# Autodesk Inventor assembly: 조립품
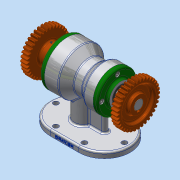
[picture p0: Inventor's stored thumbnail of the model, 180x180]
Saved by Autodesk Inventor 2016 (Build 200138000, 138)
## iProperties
Created: 2020-01
Part Number: 조립품
Document SubType Name: Assembly
Designer: woori
Author: woori
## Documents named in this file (13)
- C:\Users\woori\Desktop\700104v1001\조립품.iam
- C:\Users\woori\Desktop\700104v1001\본체.ipt
- C:\Users\woori\Desktop\700104v1001\뒤커버.ipt
- C:\Users\woori\Desktop\700104v1001\멈춤나사 M3.ipt
- C:\Users\woori\Desktop\700104v1001\베어링 6203.ipt
- C:\Users\woori\Desktop\700104v1001\베어링 6205.ipt
- C:\Users\woori\Desktop\700104v1001\볼트 M4.ipt
- C:\Users\woori\Desktop\700104v1001\앞커버.ipt
- C:\Users\woori\Desktop\700104v1001\스퍼기어.ipt
- C:\Users\woori\Desktop\700104v1001\오일 실 17 30 8.ipt
- C:\Users\woori\Desktop\700104v1001\오일 실 25 38 8.ipt
- C:\Users\woori\Desktop\700104v1001\축.ipt
- C:\Users\woori\Desktop\700104v1001\키 5 x 5 x 18.ipt
